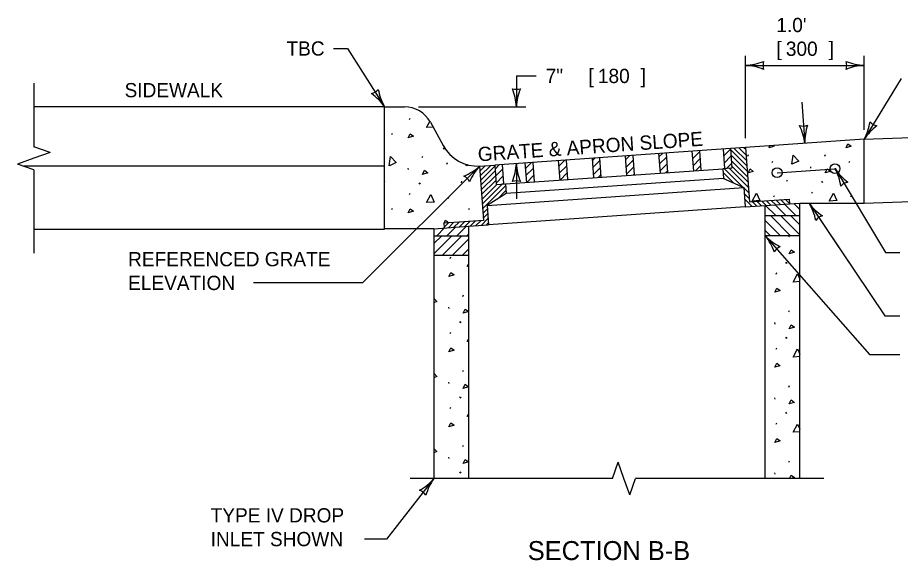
# Model space of a CAD drawing. Extents: x 49991.4 to 50048.3, y 49987.6 to 50018.3.
# Drawn here: x 50041.023 to 50044.738, y 49998.694 to 50000.979 of the extents above; entities that cross this region are included whole.
import ezdxf

# ---------------------------------------------------------------- set-up
doc = ezdxf.new("R2010")
doc.units = 0
for name, color, linetype in [('Level 1', 7, 'Continuous'), ('Level 2', 7, 'Continuous'), ('Level 3', 7, 'Continuous'), ('Level 4', 7, 'Continuous'), ('Level 6', 7, 'Continuous')]:
    doc.layers.add(name, color=color, linetype=linetype)

# ---------------------------------------------------------------- blocks, each defined once
blk = doc.blocks.new('REB')
at = {"layer": 'Level 1'}
blk.add_circle((0.0417, 0), 0.0417, dxfattribs=at)

msp = doc.modelspace()

# ---------------------------------------------------------------- linework, layer by layer
at = {"layer": 'Level 1'}
for p, q in [((50042.5673, 50000.6038), (50041.0918, 50000.6038)), ((50042.5673, 50000.0905), (50042.5673, 50000.6038)), ((50042.5673, 50000.6038), (50042.6506, 50000.6038)), ((50042.6718, 50000.55), (50042.6745, 50000.5561)), ((50042.7442, 50000.5162), (50042.7581, 50000.5424)), ((50042.7715, 50000.5184), (50042.7449, 50000.5162)), ((50042.7601, 50000.5391), (50042.8145, 50000.4401)), ((50044.5853, 50000.467), (50046.142, 50000.5214)), ((50042.596, 50000.4911), (50042.5987, 50000.4871)), ((50042.8154, 50000.4252), (50042.819, 50000.4326)), ((50044.0865, 50000.4322), (50044.0227, 50000.4277)), ((50044.0871, 50000.4233), (50044.0788, 50000.4316)), ((50044.5853, 50000.467), (50044.0865, 50000.4322)), ((50044.0865, 50000.4322), (50044.1025, 50000.2031)), ((50044.1851, 50000.4311), (50044.189, 50000.4393)), ((50044.5853, 50000.1982), (50044.5853, 50000.467)), ((50042.7259, 50000.3903), (50042.7287, 50000.3964)), ((50042.8224, 50000.4273), (50042.8154, 50000.4252)), ((50044.0227, 50000.4277), (50043.031, 50000.3583)), ((50043.5862, 50000.3149), (50043.5805, 50000.3968)), ((50043.5817, 50000.3797), (50043.6001, 50000.3981)), ((50043.6116, 50000.3989), (50043.6174, 50000.3171)), ((50043.7207, 50000.4066), (50043.7265, 50000.3248)), ((50043.7217, 50000.3927), (50043.7367, 50000.4077)), ((50043.7519, 50000.4088), (50043.7576, 50000.3269)), ((50043.861, 50000.4164), (50043.8667, 50000.3346)), ((50043.8611, 50000.4149), (50043.8627, 50000.4165)), ((50043.8632, 50000.3852), (50043.8925, 50000.4145)), ((50043.8922, 50000.4186), (50043.8979, 50000.3367)), ((50043.9916, 50000.4255), (50043.9973, 50000.3437)), ((50043.9937, 50000.3959), (50044.0229, 50000.4251)), ((50043.9957, 50000.3662), (50044.0249, 50000.3954)), ((50044.0227, 50000.4277), (50044.0284, 50000.3459)), ((50044.0919, 50000.3548), (50044.0229, 50000.4238)), ((50044.0935, 50000.332), (50044.0245, 50000.401)), ((50044.0903, 50000.3777), (50044.0391, 50000.4288)), ((50044.0887, 50000.4005), (50044.0589, 50000.4302)), ((50044.0956, 50000.3962), (50044.0983, 50000.4023)), ((50044.4198, 50000.3962), (50044.4225, 50000.4023)), ((50042.8288, 50000.3626), (50042.8315, 50000.3686)), ((50042.9111, 50000.3556), (50042.9119, 50000.3611)), ((50042.919, 50000.3591), (50042.9118, 50000.3558)), ((50042.9672, 50000.3539), (50043.031, 50000.3583)), ((50042.97, 50000.3131), (50043.0141, 50000.3572)), ((50043.031, 50000.3583), (50043.0367, 50000.2765)), ((50043.0322, 50000.3418), (50043.05, 50000.3597)), ((50043.0621, 50000.3605), (50043.0678, 50000.2787)), ((50043.1653, 50000.2855), (50043.1596, 50000.3673)), ((50043.1612, 50000.345), (50043.1853, 50000.3691)), ((50043.1908, 50000.3695), (50043.1965, 50000.2877)), ((50043.3056, 50000.2953), (50043.2999, 50000.3771)), ((50043.3015, 50000.3548), (50043.3256, 50000.3789)), ((50043.3311, 50000.3793), (50043.3368, 50000.2975)), ((50043.4402, 50000.387), (50043.4459, 50000.3051)), ((50043.4409, 50000.3764), (50043.4523, 50000.3878)), ((50043.443, 50000.3467), (50043.4723, 50000.376)), ((50043.4713, 50000.3891), (50043.4771, 50000.3073)), ((50043.5837, 50000.35), (50043.613, 50000.3792)), ((50043.7238, 50000.363), (50043.7531, 50000.3923)), ((50043.7259, 50000.3332), (50043.7551, 50000.3625)), ((50043.8653, 50000.3555), (50043.8946, 50000.3847)), ((50044.0057, 50000.3443), (50044.027, 50000.3656)), ((50044.0951, 50000.3092), (50044.0261, 50000.3782)), ((50044.1985, 50000.3685), (50044.2012, 50000.3746)), ((50044.5226, 50000.3685), (50044.5253, 50000.3746)), ((50042.5673, 50000.3537), (50041.0486, 50000.3537)), ((50042.6655, 50000.3456), (50042.6662, 50000.3395)), ((50042.9672, 50000.3539), (50042.9832, 50000.1248)), ((50042.9686, 50000.333), (50042.9913, 50000.3556)), ((50042.9714, 50000.2933), (50043.0314, 50000.3532)), ((50042.9728, 50000.2735), (50043.0327, 50000.3334)), ((50043.0342, 50000.3121), (50043.0634, 50000.3413)), ((50043.1633, 50000.3153), (50043.1925, 50000.3445)), ((50043.3035, 50000.3251), (50043.3328, 50000.3543)), ((50043.3056, 50000.2953), (50043.3349, 50000.3246)), ((50043.4451, 50000.317), (50043.4743, 50000.3462)), ((50043.5858, 50000.3202), (50043.6151, 50000.3495)), ((50043.6143, 50000.3169), (50043.6172, 50000.3198)), ((50043.7509, 50000.3265), (50043.7572, 50000.3328)), ((50043.8769, 50000.3353), (50043.8966, 50000.355)), ((50044.0284, 50000.3459), (50043.9908, 50000.3432)), ((50043.9908, 50000.3432), (50043.9936, 50000.3023)), ((50044.0366, 50000.2828), (50043.9918, 50000.3276)), ((50044.0754, 50000.2653), (50043.997, 50000.3437)), ((50044.0983, 50000.2636), (50044.0168, 50000.3451)), ((50044.0967, 50000.2864), (50044.0277, 50000.3554)), ((50044.2192, 50000.3263), (50044.4606, 50000.3432)), ((50044.3594, 50000.3515), (50044.36, 50000.3454)), ((50042.5673, 50000.2863), (50042.5689, 50000.2902)), ((50042.7117, 50000.2841), (50042.7144, 50000.28)), ((50042.7144, 50000.2825), (50042.7171, 50000.2785)), ((50042.8904, 50000.2841), (50042.8931, 50000.2902)), ((50042.9742, 50000.2536), (50043.0341, 50000.3136)), ((50042.9756, 50000.2338), (50043.0355, 50000.2938)), ((50043.0363, 50000.2823), (50043.0655, 50000.3115)), ((50043.1653, 50000.2855), (50043.1946, 50000.3148)), ((50043.4665, 50000.3066), (50043.4764, 50000.3165)), ((50043.9978, 50000.3004), (50043.9934, 50000.3048)), ((50043.9936, 50000.3023), (50044.0785, 50000.2639)), ((50044.2601, 50000.29), (50044.2628, 50000.2961)), ((50044.4055, 50000.29), (50044.4082, 50000.2859)), ((50044.4082, 50000.2884), (50044.411, 50000.2844)), ((50042.977, 50000.214), (50043.0397, 50000.2767)), ((50042.9783, 50000.1942), (50043.0625, 50000.2783)), ((50042.9797, 50000.1743), (50043.0766, 50000.2712)), ((50042.9985, 50000.1883), (50044.0785, 50000.2639)), ((50043.0367, 50000.2765), (50043.076, 50000.2793)), ((50043.0421, 50000.2155), (50043.0779, 50000.2513)), ((50043.0642, 50000.2784), (50043.0676, 50000.2818)), ((50043.076, 50000.2793), (50043.0789, 50000.2384)), ((50044.0785, 50000.2639), (50044.0842, 50000.182)), ((50044.0999, 50000.2408), (50044.0787, 50000.262)), ((50044.3656, 50000.2398), (50044.3683, 50000.2459)), ((50044.5853, 50000.1982), (50046.142, 50000.2526)), ((50042.6718, 50000.2339), (50042.6745, 50000.24)), ((50042.8356, 50000.2183), (50042.8383, 50000.2244)), ((50043.0789, 50000.2384), (50042.9985, 50000.1883)), ((50044.1015, 50000.218), (50044.0803, 50000.2392)), ((50044.1141, 50000.1841), (50044.0818, 50000.2164)), ((50044.1025, 50000.2031), (50044.2694, 50000.2147)), ((50044.2133, 50000.1911), (50044.1948, 50000.2095)), ((50044.2052, 50000.2243), (50044.2079, 50000.2304)), ((50044.2331, 50000.1924), (50044.2146, 50000.2109)), ((50044.2529, 50000.1938), (50044.2345, 50000.2123)), ((50044.2727, 50000.1952), (50044.2543, 50000.2137)), ((50044.2694, 50000.2147), (50044.2708, 50000.1951)), ((50044.5294, 50000.2243), (50044.5321, 50000.2304)), ((50042.596, 50000.175), (50042.5987, 50000.171)), ((50042.9202, 50000.175), (50042.9229, 50000.171)), ((50042.9811, 50000.1545), (50042.9996, 50000.173)), ((50042.9985, 50000.1883), (50043.0042, 50000.1065)), ((50044.0842, 50000.182), (50043.0042, 50000.1065)), ((50044.0842, 50000.182), (50044.1692, 50000.188)), ((50044.1339, 50000.1855), (50044.1155, 50000.204)), ((50044.1538, 50000.1869), (50044.1353, 50000.2053)), ((50044.1736, 50000.1883), (50044.1552, 50000.2067)), ((50044.2146, 50000.1443), (50044.1708, 50000.1881)), ((50044.1934, 50000.1897), (50044.175, 50000.2081)), ((50044.2571, 50000.1443), (50044.2105, 50000.1909)), ((50044.2995, 50000.1443), (50044.2501, 50000.1936)), ((50044.3152, 50000.171), (50044.2898, 50000.1964)), ((50044.3152, 49999.0386), (50044.3152, 50000.1982)), ((50044.3152, 50000.1982), (50044.5853, 50000.1982)), ((50042.9825, 50000.1347), (50043.0009, 50000.1531)), ((50044.3152, 50000.1443), (50044.1692, 50000.1443)), ((50044.276, 50000.0609), (50044.1927, 50000.1443)), ((50044.3152, 50000.0642), (50044.2351, 50000.1443)), ((50044.3152, 50000.1066), (50044.2775, 50000.1443)), ((50042.7749, 50000.0905), (50042.9209, 50000.1007)), ((50042.8154, 50000.1091), (50042.8164, 50000.1112)), ((50042.8165, 50000.1094), (50042.8154, 50000.1091)), ((50042.9832, 50000.1248), (50042.8163, 50000.1131)), ((50042.8163, 50000.1131), (50042.8177, 50000.0935)), ((50042.8174, 50000.0969), (50042.835, 50000.1144)), ((50042.8293, 50000.0609), (50042.8651, 50000.0968)), ((50042.8366, 50000.0948), (50042.8578, 50000.116)), ((50042.8594, 50000.0964), (50042.8806, 50000.1176)), ((50042.8717, 50000.0609), (50042.9107, 50000.1)), ((50042.8822, 50000.098), (50042.9034, 50000.1192)), ((50042.905, 50000.0996), (50042.9262, 50000.1208)), ((50042.9209, 50000.1007), (50043.0042, 50000.1065)), ((50042.9209, 50000.1007), (50042.9209, 49999.0386)), ((50042.9278, 50000.1012), (50042.949, 50000.1224)), ((50042.9506, 50000.1028), (50042.9718, 50000.124)), ((50042.9734, 50000.1044), (50043.0023, 50000.1333)), ((50042.9962, 50000.106), (50043.0037, 50000.1135)), ((50044.2336, 50000.0609), (50044.1692, 50000.1253)), ((50042.5673, 50000.0869), (50041.0918, 50000.0869)), ((50042.7749, 50000.0905), (50042.5673, 50000.0905)), ((50042.7749, 50000.0905), (50042.7749, 49999.0386)), ((50042.7749, 50000.0609), (50042.9209, 50000.0609)), ((50042.7749, 49999.9853), (50042.8505, 50000.0609)), ((50042.7749, 50000.0278), (50042.8081, 50000.0609)), ((50042.7868, 50000.0609), (50042.8195, 50000.0936)), ((50042.8096, 49999.9776), (50042.8929, 50000.0609)), ((50042.9141, 50000.0609), (50042.9209, 50000.0677)), ((50044.1912, 50000.0609), (50044.1692, 50000.0829)), ((50044.3152, 50000.0609), (50044.1692, 50000.0609)), ((50044.269, 50000.056), (50044.2712, 50000.0609)), ((50042.852, 49999.9776), (50042.9209, 50000.0465)), ((50042.8944, 49999.9776), (50042.9209, 50000.004)), ((50042.9209, 49999.9776), (50042.7749, 49999.9776)), ((50042.843, 49999.9653), (50042.8457, 49999.9714)), ((50044.2548, 49999.9497), (50044.2575, 49999.9457)), ((50042.9154, 49999.9314), (50042.9209, 49999.9417)), ((50042.9209, 49999.9318), (50042.9161, 49999.9314)), ((50044.2575, 49999.9482), (50044.2602, 49999.9441)), ((50044.2149, 49999.8996), (50044.2176, 49999.9056)), ((50044.3152, 49999.868), (50044.288, 49999.8657)), ((50042.8971, 49999.8056), (50042.8998, 49999.8117)), ((50042.8367, 49999.7608), (50042.8374, 49999.7547)), ((50044.269, 49999.7399), (50044.2717, 49999.746)), ((50042.8829, 49999.6993), (50042.8856, 49999.6953)), ((50042.8856, 49999.6978), (50042.8883, 49999.6937)), ((50044.2086, 49999.6951), (50044.2093, 49999.689)), ((50042.843, 49999.6492), (50042.8457, 49999.6553)), ((50042.9154, 49999.6153), (50042.9209, 49999.6257)), ((50042.9209, 49999.6158), (50042.9161, 49999.6153)), ((50044.2548, 49999.6336), (50044.2575, 49999.6296)), ((50044.2149, 49999.5835), (50044.2176, 49999.5896)), ((50044.3152, 49999.552), (50044.288, 49999.5496)), ((50042.8971, 49999.4895), (50042.8998, 49999.4956)), ((50042.8367, 49999.4447), (50042.8374, 49999.4387)), ((50044.269, 49999.4238), (50044.2717, 49999.4299)), ((50042.8829, 49999.3832), (50042.8856, 49999.3792)), ((50042.8856, 49999.3817), (50042.8883, 49999.3776)), ((50044.2086, 49999.379), (50044.2093, 49999.3729)), ((50042.843, 49999.3331), (50042.8457, 49999.3392)), ((50044.2548, 49999.3175), (50044.2575, 49999.3135)), ((50042.9154, 49999.2993), (50042.9209, 49999.3096)), ((50042.9209, 49999.2997), (50042.9161, 49999.2993)), ((50044.2575, 49999.316), (50044.2602, 49999.3119)), ((50044.2149, 49999.2674), (50044.2176, 49999.2735)), ((50044.3152, 49999.2359), (50044.288, 49999.2336)), ((50042.8971, 49999.1734), (50042.8998, 49999.1795)), ((50042.8367, 49999.1287), (50042.8374, 49999.1226)), ((50044.269, 49999.1077), (50044.2717, 49999.1138)), ((50042.8829, 49999.0672), (50042.8856, 49999.0631)), ((50042.8856, 49999.0656), (50042.8883, 49999.0616)), ((50044.2086, 49999.0629), (50044.2093, 49999.0569))]:
    msp.add_line(p, q, dxfattribs=at)
for points in [[(50042.6671, 50000.4735), (50042.6752, 50000.4904), (50042.6887, 50000.4803), (50042.6671, 50000.4735)], [(50044.2034, 50000.4403), (50044.2067, 50000.4379), (50044.1851, 50000.4311)], [(50044.5092, 50000.4311), (50044.5173, 50000.448), (50044.5309, 50000.4379), (50044.5092, 50000.4311)], [(50042.587, 50000.3556), (50042.5923, 50000.3942), (50042.6166, 50000.3692), (50042.5876, 50000.3558)], [(50044.2808, 50000.3615), (50044.2862, 50000.4002), (50044.3104, 50000.3751), (50044.2814, 50000.3617)], [(50042.7273, 50000.3192), (50042.7354, 50000.3362), (50042.749, 50000.326), (50042.7273, 50000.3192)], [(50044.097, 50000.3252), (50044.1051, 50000.3421), (50044.1186, 50000.3319), (50044.097, 50000.3252)], [(50044.4211, 50000.3252), (50044.4292, 50000.3421), (50044.4428, 50000.3319), (50044.4211, 50000.3252)], [(50042.7442, 50000.2001), (50042.7625, 50000.2346), (50042.7767, 50000.2028), (50042.7449, 50000.2001)], [(50044.1139, 50000.206), (50044.1322, 50000.2405), (50044.1464, 50000.2087), (50044.1146, 50000.206)], [(50044.438, 50000.206), (50044.4563, 50000.2405), (50044.4705, 50000.2087), (50044.4387, 50000.206)], [(50042.6671, 50000.1574), (50042.6752, 50000.1744), (50042.6887, 50000.1642), (50042.6671, 50000.1574)], [(50044.1692, 50000.188), (50044.3152, 50000.1982)], [(50044.1692, 49999.0386), (50044.1692, 50000.188)], [(50042.8174, 50000.1132), (50042.8235, 50000.126), (50042.8371, 50000.1158), (50042.8318, 50000.1142)], [(50044.2704, 49999.9849), (50044.2785, 50000.0018), (50044.292, 49999.9917), (50044.2704, 49999.9849)], [(50042.8383, 49999.8888), (50042.8464, 49999.9057), (50042.8599, 49999.8956), (50042.8383, 49999.8888)], [(50044.2873, 49999.8657), (50044.3056, 49999.9002), (50044.3152, 49999.8786)], [(50044.2101, 49999.8231), (50044.2183, 49999.84), (50044.2318, 49999.8299), (50044.2101, 49999.8231)], [(50042.7749, 49999.7978), (50042.7878, 49999.7845), (50042.7749, 49999.7785)], [(50042.8985, 49999.7345), (50042.9066, 49999.7514), (50042.9201, 49999.7413), (50042.8985, 49999.7345)], [(50044.2704, 49999.6688), (50044.2785, 49999.6857), (50044.292, 49999.6756), (50044.2704, 49999.6688)], [(50042.8383, 49999.5727), (50042.8464, 49999.5896), (50042.8599, 49999.5795), (50042.8383, 49999.5727)], [(50044.2873, 49999.5496), (50044.3056, 49999.5841), (50044.3152, 49999.5625)], [(50044.2101, 49999.507), (50044.2183, 49999.5239), (50044.2318, 49999.5138), (50044.2101, 49999.507)], [(50042.7749, 49999.4817), (50042.7878, 49999.4684), (50042.7749, 49999.4624)], [(50042.8985, 49999.4184), (50042.9066, 49999.4353), (50042.9201, 49999.4252), (50042.8985, 49999.4184)], [(50044.2704, 49999.3527), (50044.2785, 49999.3696), (50044.292, 49999.3595), (50044.2704, 49999.3527)], [(50042.8383, 49999.2566), (50042.8464, 49999.2735), (50042.8599, 49999.2634), (50042.8383, 49999.2566)], [(50044.2873, 49999.2336), (50044.3056, 49999.2681), (50044.3152, 49999.2464)], [(50044.2101, 49999.1909), (50044.2183, 49999.2078), (50044.2318, 49999.1977), (50044.2101, 49999.1909)], [(50042.7749, 49999.1656), (50042.7878, 49999.1523), (50042.7749, 49999.1463)], [(50042.8985, 49999.1023), (50042.9066, 49999.1193), (50042.9201, 49999.1091), (50042.8985, 49999.1023)], [(50044.2713, 49999.0386), (50044.2785, 49999.0536), (50044.292, 49999.0434), (50044.2768, 49999.0386)]]:
    msp.add_lwpolyline(points, dxfattribs=at)
for centre, radius, start, end in [((50042.6506, 50000.4789), 0.125, 28.801, 90), ((50042.9605, 50000.5204), 0.1666, 208.7914, 272.2906)]:
    msp.add_arc(centre, radius, start, end, dxfattribs=at)
at = {"layer": 'Level 3'}
for p, q in [((50044.0865, 50000.4722), (50044.0865, 50000.8181)), ((50044.5853, 50000.507), (50044.5853, 50000.8181)), ((50044.0865, 50000.7781), (50044.5853, 50000.7781)), ((50043.122, 50000.7336), (50043.122, 50000.6038)), ((50043.122, 50000.7336), (50043.2053, 50000.7336)), ((50044.7406, 50000.7229), (50044.5853, 50000.467)), ((50044.3238, 50000.6226), (50044.3359, 50000.4496)), ((50042.5673, 50000.6024), (50042.5679, 50000.6038)), ((50042.7095, 50000.6038), (50043.162, 50000.6038)), ((50043.122, 50000.3647), (50043.122, 50000.2163)), ((50042.9672, 50000.3539), (50042.4742, 49999.8622)), ((50044.4628, 50000.3434), (50044.675, 49999.9896)), ((50044.5842, 50000.29), (50044.5853, 50000.2924)), ((50044.3535, 50000.1982), (50044.5224, 49999.9469)), ((50044.3535, 50000.1982), (50044.5224, 49999.9469)), ((50044.3535, 50000.1982), (50044.6725, 49999.7238)), ((50044.1692, 50000.0609), (50044.6079, 49999.5614)), ((50044.675, 49999.9896), (50044.735, 49999.9896)), ((50042.4742, 49999.8622), (50042.0154, 49999.8622)), ((50044.6725, 49999.7238), (50044.735, 49999.7238)), ((50044.2575, 49999.6321), (50044.2602, 49999.628)), ((50044.6079, 49999.5614), (50044.735, 49999.5614))]:
    msp.add_line(p, q, dxfattribs=at)
for points in [[(50042.3518, 50000.8492), (50042.4118, 50000.8492), (50042.5673, 50000.6038)], [(50042.7749, 49999.0386), (50042.5748, 49998.7839)], [(50042.5748, 49998.7839), (50042.4827, 49998.7839)]]:
    msp.add_lwpolyline(points, dxfattribs=at)
for centre, radius, start, end in [((50044.075, 50001.0108), 0.233, 272.8273, 292.0772), ((50044.0773, 50000.556), 0.2223, 67.456, 87.6395), ((50044.2147, 50000.7781), 0.0548, 162.1388, 197.8612), ((50044.5944, 50001.0002), 0.2223, 247.456, 267.6395), ((50044.4571, 50000.7781), 0.0548, 342.1388, 17.8612), ((50044.5968, 50000.5454), 0.233, 92.8273, 112.0772), ((50042.4986, 50000.7121), 0.0548, 284.4928, 320.2152), ((50042.4986, 50000.7121), 0.0548, 284.4928, 320.2152), ((50042.3768, 50000.4696), 0.233, 35.1813, 54.4312), ((50042.3768, 50000.4696), 0.233, 35.1813, 54.4312), ((50042.7598, 50000.715), 0.2223, 189.81, 209.9935), ((50042.7598, 50000.715), 0.2223, 189.81, 209.9935), ((50043.122, 50000.732), 0.0548, 252.1388, 287.8612), ((50042.8893, 50000.5923), 0.233, 2.8273, 22.0772), ((50043.3441, 50000.5947), 0.2223, 157.456, 177.6395), ((50044.3269, 50000.5775), 0.0548, 256.1388, 291.8612), ((50044.1045, 50000.4219), 0.233, 6.8273, 26.0772), ((50044.5581, 50000.456), 0.2223, 161.456, 181.6395), ((50044.3804, 50000.5779), 0.233, 331.574, 350.8239), ((50044.7704, 50000.344), 0.2223, 126.2027, 146.3862), ((50044.6518, 50000.5766), 0.0548, 220.8855, 256.6079), ((50042.8999, 50000.3739), 0.2223, 337.456, 357.6395), ((50043.3547, 50000.3762), 0.233, 182.8273, 202.0772), ((50042.8168, 50000.5176), 0.2223, 292.3834, 312.5669), ((50043.1397, 50000.1973), 0.233, 137.7547, 157.0046), ((50044.2676, 50000.2369), 0.2223, 8.412, 28.5955), ((50044.6564, 50000.4729), 0.233, 213.7833, 233.0331), ((50042.8764, 50000.2634), 0.0548, 27.0662, 62.7886), ((50043.122, 50000.2365), 0.0548, 72.1388, 107.8612), ((50044.5287, 50000.2334), 0.0548, 103.0948, 138.8171), ((50044.164, 50000.0818), 0.2223, 11.3731, 31.5566), ((50044.5402, 50000.3376), 0.233, 216.7444, 235.9942), ((50044.164, 50000.0818), 0.2223, 11.3731, 31.5566), ((50044.5402, 50000.3376), 0.233, 216.7444, 235.9942), ((50044.164, 50000.0818), 0.2223, 11.3731, 31.5566), ((50044.5402, 50000.3376), 0.233, 216.7444, 235.9942), ((50044.425, 50000.0918), 0.0548, 106.0559, 141.7782), ((50044.425, 50000.0918), 0.0548, 106.0559, 141.7782), ((50044.425, 50000.0918), 0.0548, 106.0559, 141.7782), ((50043.9963, 49999.9213), 0.2223, 18.7421, 38.9256), ((50044.3365, 50000.2231), 0.233, 224.1134, 243.3633), ((50044.2538, 49999.9646), 0.0548, 113.4249, 149.1473), ((50042.6058, 49999.183), 0.2223, 299.3177, 319.5012), ((50042.965, 49998.904), 0.233, 144.689, 163.9389), ((50042.6957, 49998.9378), 0.0548, 34.0005, 69.7229)]:
    msp.add_arc(centre, radius, start, end, dxfattribs=at)
at = {"layer": 'Level 4'}
for p, q in [((50043.076, 50000.2793), (50043.9907, 50000.3432)), ((50043.9936, 50000.3023), (50043.0789, 50000.2384))]:
    msp.add_line(p, q, dxfattribs=at)
at = {"layer": 'Level 6'}
for p, q in [((50041.0918, 50000.7038), (50041.0918, 50000.4356)), ((50041.1604, 50000.4113), (50041.0918, 50000.4356)), ((50041.1604, 50000.4113), (50041.0918, 50000.387)), ((50041.0918, 50000.387), (50041.0232, 50000.3627)), ((50041.0918, 50000.3384), (50041.0232, 50000.3627)), ((50041.0918, 50000.3384), (50041.0918, 49999.9869)), ((50043.5261, 49999.0386), (50043.5504, 49999.1072)), ((50043.5747, 49999.0386), (50043.5504, 49999.1072)), ((50043.5261, 49999.0386), (50042.6749, 49999.0386)), ((50043.599, 49998.97), (50043.5747, 49999.0386)), ((50043.599, 49998.97), (50043.6233, 49999.0386)), ((50044.4152, 49999.0386), (50043.6233, 49999.0386))]:
    msp.add_line(p, q, dxfattribs=at)

# ---------------------------------------------------------------- block references
at = {"layer": 'Level 2', "xscale": 0.5, "yscale": 0.5}
for p in [(50044.4419, 50000.3434), (50044.1984, 50000.3263)]:
    msp.add_blockref('REB', p, dxfattribs=at)

# ---------------------------------------------------------------- texts
at = {"layer": 'Level 2'}
for s, height, p in [("1.0' ", 0.06, (50044.216, 50000.9181)), ('TBC', 0.06, (50042.1545, 50000.8192)), ('[', 0.06, (50044.2162, 50000.8181)), ('300', 0.06, (50044.2559, 50000.8181)), (']', 0.06, (50044.4359, 50000.8181)), ('[', 0.06, (50043.4253, 50000.7036)), (']', 0.06, (50043.645, 50000.7036)), ('7" ', 0.06, (50043.2453, 50000.7036)), ('180', 0.06, (50043.465, 50000.7036)), ('SIDEWALK', 0.0599, (50041.4733, 50000.6438)), ('REFERENCED GRATE', 0.06, (50041.4881, 49999.9322)), ('ELEVATION', 0.06, (50041.4881, 49999.8322)), ('TYPE IV DROP', 0.06, (50041.8354, 49998.8539)), ('INLET SHOWN', 0.06, (50041.8354, 49998.7539)), ('SECTION B-B', 0.08, (50043.1699, 49998.6954))]:
    msp.add_text(s, height=height, dxfattribs=at).set_placement(p)
msp.add_text('GRATE & APRON SLOPE', height=0.06, rotation=4, dxfattribs=at).set_placement((50042.9617, 50000.3735))

doc.saveas('drawing.dxf')
